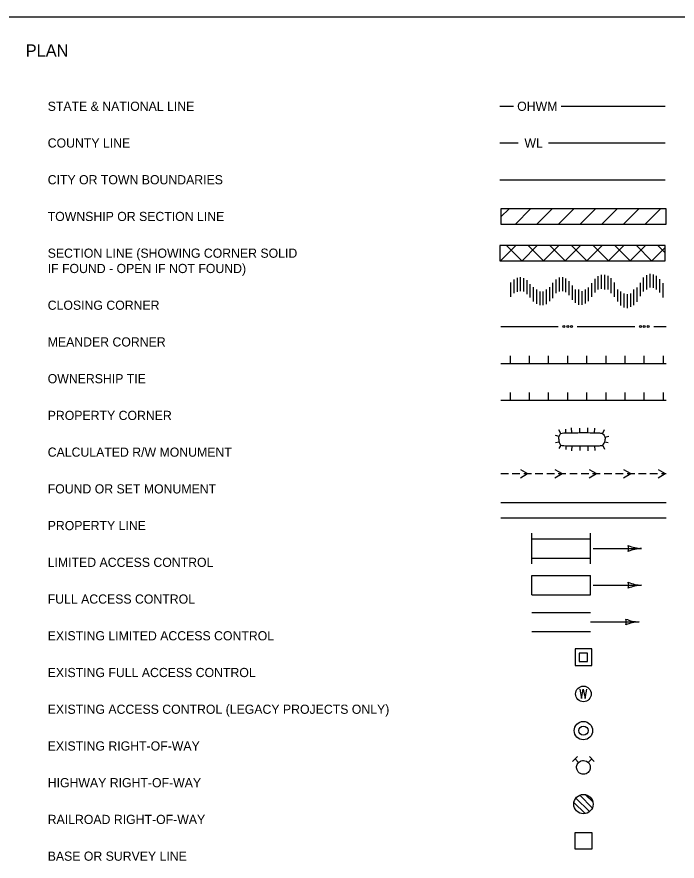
# Model space of a CAD drawing. Extents: x 49991.4 to 50021, y 49987.6 to 50011.4.
# Drawn here: x 50005.13 to 50009.45, y 49993.48 to 49999 of the extents above; entities that cross this region are included whole.
import ezdxf

# ---------------------------------------------------------------- set-up
doc = ezdxf.new("R2010")
doc.units = 0
doc.layers.add('Level 1', color=7, linetype='Continuous')
doc.layers.add('Level 2', color=7, linetype='Continuous')

msp = doc.modelspace()

# ---------------------------------------------------------------- linework, layer by layer
at = {"layer": 'Level 1'}
for p, q in [((50008.2879, 49998.4152), (50008.3758, 49998.4152)), ((50008.6879, 49998.4152), (50009.3679, 49998.4152)), ((50008.2879, 49998.1752), (50008.4057, 49998.1752)), ((50008.6047, 49998.1752), (50009.3679, 49998.1752)), ((50008.2879, 49997.9352), (50009.3679, 49997.9352)), ((50008.2935, 49997.6918), (50008.347, 49997.7452)), ((50009.3735, 49997.7452), (50008.2935, 49997.7452)), ((50008.2935, 49997.7452), (50008.2935, 49997.6452)), ((50008.3884, 49997.6452), (50008.4884, 49997.7452)), ((50008.5298, 49997.6452), (50008.6298, 49997.7452)), ((50008.6713, 49997.6452), (50008.7713, 49997.7452)), ((50008.8127, 49997.6452), (50008.9127, 49997.7452)), ((50008.9541, 49997.6452), (50009.0541, 49997.7452)), ((50009.0955, 49997.6452), (50009.1955, 49997.7452)), ((50009.2369, 49997.6452), (50009.3369, 49997.7452)), ((50009.3735, 49997.6452), (50009.3735, 49997.7452)), ((50008.2935, 49997.6452), (50009.3735, 49997.6452)), ((50009.3679, 49997.5052), (50008.2879, 49997.5052)), ((50008.2879, 49997.5052), (50008.2879, 49997.4052)), ((50008.2906, 49997.4052), (50008.3906, 49997.5052)), ((50008.3309, 49997.5052), (50008.4309, 49997.4052)), ((50008.432, 49997.4052), (50008.532, 49997.5052)), ((50008.4723, 49997.5052), (50008.5723, 49997.4052)), ((50008.5734, 49997.4052), (50008.6734, 49997.5052)), ((50008.6137, 49997.5052), (50008.7137, 49997.4052)), ((50008.7148, 49997.4052), (50008.8148, 49997.5052)), ((50008.7551, 49997.5052), (50008.8551, 49997.4052)), ((50008.8562, 49997.4052), (50008.9562, 49997.5052)), ((50008.8966, 49997.5052), (50008.9966, 49997.4052)), ((50008.9977, 49997.4052), (50009.0977, 49997.5052)), ((50009.038, 49997.5052), (50009.138, 49997.4052)), ((50009.1391, 49997.4052), (50009.2391, 49997.5052)), ((50009.1794, 49997.5052), (50009.2794, 49997.4052)), ((50009.2805, 49997.4052), (50009.3679, 49997.4926)), ((50009.3208, 49997.5052), (50009.3679, 49997.4582)), ((50009.3679, 49997.4052), (50009.3679, 49997.5052)), ((50008.2879, 49997.4068), (50008.2894, 49997.4052)), ((50008.2879, 49997.4052), (50009.3679, 49997.4052)), ((50008.3779, 49997.2838), (50008.3779, 49997.1935)), ((50008.3991, 49997.2932), (50008.3991, 49997.2034)), ((50008.4203, 49997.298), (50008.4203, 49997.208)), ((50008.4415, 49997.2924), (50008.4415, 49997.204)), ((50008.4626, 49997.2792), (50008.4626, 49997.188)), ((50008.6532, 49997.2835), (50008.6532, 49997.1945)), ((50008.6744, 49997.2959), (50008.6744, 49997.2058)), ((50008.6744, 49997.2956), (50008.6744, 49997.2061)), ((50008.6956, 49997.298), (50008.6956, 49997.208)), ((50008.7168, 49997.2908), (50008.7168, 49997.201)), ((50008.7379, 49997.2733), (50008.7379, 49997.1804)), ((50008.9073, 49997.2879), (50008.9073, 49997.1973)), ((50008.9285, 49997.3058), (50008.9285, 49997.2173)), ((50008.9497, 49997.3134), (50008.9497, 49997.2224)), ((50008.9709, 49997.3143), (50008.9709, 49997.2173)), ((50008.992, 49997.3064), (50008.992, 49997.2173)), ((50009.0132, 49997.2928), (50009.0132, 49997.1946)), ((50009.225, 49997.2953), (50009.225, 49997.2046)), ((50009.2462, 49997.3106), (50009.2462, 49997.2173)), ((50009.2673, 49997.3203), (50009.2673, 49997.2299)), ((50009.2885, 49997.3166), (50009.2885, 49997.2277)), ((50009.3097, 49997.3063), (50009.3097, 49997.2173)), ((50009.3309, 49997.285), (50009.3309, 49997.1974)), ((50008.3568, 49997.2631), (50008.3568, 49997.1702)), ((50008.4838, 49997.2528), (50008.4838, 49997.1656)), ((50008.505, 49997.2336), (50008.505, 49997.1395)), ((50008.5262, 49997.2173), (50008.5262, 49997.1245)), ((50008.5897, 49997.2173), (50008.5897, 49997.1231)), ((50008.6109, 49997.2322), (50008.6109, 49997.141)), ((50008.632, 49997.2615), (50008.632, 49997.161)), ((50008.7591, 49997.2441), (50008.7591, 49997.1507)), ((50008.7803, 49997.2173), (50008.7803, 49997.1313)), ((50008.8015, 49997.2173), (50008.8015, 49997.1169)), ((50008.8438, 49997.2173), (50008.8438, 49997.1266)), ((50008.865, 49997.2314), (50008.865, 49997.1417)), ((50008.8862, 49997.2593), (50008.8862, 49997.1693)), ((50009.0344, 49997.264), (50009.0344, 49997.1737)), ((50009.0344, 49997.2622), (50009.0344, 49997.1709)), ((50009.0556, 49997.2173), (50009.0556, 49997.1388)), ((50009.1615, 49997.2173), (50009.1615, 49997.1159)), ((50009.1826, 49997.2318), (50009.1826, 49997.1362)), ((50009.2038, 49997.2615), (50009.2038, 49997.1741)), ((50009.352, 49997.2601), (50009.352, 49997.1665)), ((50008.5473, 49997.205), (50008.5473, 49997.1157)), ((50008.5685, 49997.2047), (50008.5685, 49997.1146)), ((50008.8226, 49997.207), (50008.8226, 49997.1182)), ((50009.0768, 49997.2039), (50009.0768, 49997.1136)), ((50009.0979, 49997.1913), (50009.0979, 49997.1004)), ((50009.1191, 49997.1868), (50009.1191, 49997.0969)), ((50009.1403, 49997.1918), (50009.1403, 49997.1042)), ((50008.2935, 49996.9752), (50008.6685, 49996.9752)), ((50008.7935, 49996.9752), (50009.1685, 49996.9752)), ((50009.2935, 49996.9752), (50009.3735, 49996.9752)), ((50008.356, 49996.7352), (50008.356, 49996.7852)), ((50008.481, 49996.7352), (50008.481, 49996.7852)), ((50008.606, 49996.7352), (50008.606, 49996.7852)), ((50008.731, 49996.7352), (50008.731, 49996.7852)), ((50008.856, 49996.7352), (50008.856, 49996.7852)), ((50008.981, 49996.7352), (50008.981, 49996.7852)), ((50009.106, 49996.7352), (50009.106, 49996.7852)), ((50009.231, 49996.7352), (50009.231, 49996.7852)), ((50009.356, 49996.7352), (50009.356, 49996.7852)), ((50008.2935, 49996.7352), (50009.3735, 49996.7352)), ((50008.356, 49996.4952), (50008.356, 49996.5452)), ((50008.481, 49996.4952), (50008.481, 49996.5452)), ((50008.606, 49996.4952), (50008.606, 49996.5452)), ((50008.731, 49996.4952), (50008.731, 49996.5452)), ((50008.856, 49996.4952), (50008.856, 49996.5452)), ((50008.981, 49996.4952), (50008.981, 49996.5452)), ((50009.106, 49996.4952), (50009.106, 49996.5452)), ((50009.231, 49996.4952), (50009.231, 49996.5452)), ((50009.356, 49996.4952), (50009.356, 49996.5452)), ((50008.2935, 49996.4952), (50009.3735, 49996.4952)), ((50008.6851, 49996.276), (50008.6735, 49996.2999)), ((50008.7193, 49996.2809), (50008.7184, 49996.306)), ((50008.7567, 49996.2819), (50008.7565, 49996.3134)), ((50008.8107, 49996.2822), (50008.8106, 49996.3124)), ((50008.8615, 49996.2824), (50008.8617, 49996.3134)), ((50008.9068, 49996.2819), (50008.9075, 49996.3123)), ((50008.9575, 49996.2758), (50008.971, 49996.3027)), ((50008.6749, 49996.2583), (50008.6502, 49996.2629)), ((50008.9732, 49996.2229), (50008.9962, 49996.218)), ((50008.9735, 49996.2537), (50008.9989, 49996.2591)), ((50008.6749, 49996.2195), (50008.6502, 49996.2149)), ((50008.6851, 49996.2017), (50008.6735, 49996.1779)), ((50008.7193, 49996.1969), (50008.7184, 49996.1717)), ((50008.7567, 49996.1959), (50008.7565, 49996.1643)), ((50008.8107, 49996.1955), (50008.8106, 49996.1654)), ((50008.8615, 49996.1953), (50008.8617, 49996.1643)), ((50008.9068, 49996.1959), (50008.9075, 49996.1654)), ((50008.9575, 49996.202), (50008.971, 49996.1751)), ((50008.2935, 49996.0152), (50008.3435, 49996.0152)), ((50008.3685, 49996.0152), (50008.4185, 49996.0152)), ((50008.4211, 49996.0426), (50008.4685, 49996.0152)), ((50008.4211, 49995.9879), (50008.4685, 49996.0152)), ((50008.4435, 49996.0152), (50008.4935, 49996.0152)), ((50008.5185, 49996.0152), (50008.5685, 49996.0152)), ((50008.5935, 49996.0152), (50008.6435, 49996.0152)), ((50008.6461, 49996.0426), (50008.6935, 49996.0152)), ((50008.6461, 49995.9879), (50008.6935, 49996.0152)), ((50008.6685, 49996.0152), (50008.7185, 49996.0152)), ((50008.7435, 49996.0152), (50008.7935, 49996.0152)), ((50008.8185, 49996.0152), (50008.8685, 49996.0152)), ((50008.8711, 49996.0426), (50008.9185, 49996.0152)), ((50008.8711, 49995.9879), (50008.9185, 49996.0152)), ((50008.8935, 49996.0152), (50008.9435, 49996.0152)), ((50008.9685, 49996.0152), (50009.0185, 49996.0152)), ((50009.0435, 49996.0152), (50009.0935, 49996.0152)), ((50009.0961, 49996.0426), (50009.1435, 49996.0152)), ((50009.0961, 49995.9879), (50009.1435, 49996.0152)), ((50009.1185, 49996.0152), (50009.1685, 49996.0152)), ((50009.1935, 49996.0152), (50009.2435, 49996.0152)), ((50009.2685, 49996.0152), (50009.3185, 49996.0152)), ((50009.3211, 49996.0426), (50009.3685, 49996.0152)), ((50009.3211, 49995.9879), (50009.3685, 49996.0152)), ((50009.3435, 49996.0152), (50009.3735, 49996.0152)), ((50008.2935, 49995.8252), (50009.3735, 49995.8252)), ((50008.2935, 49995.7252), (50009.3735, 49995.7252)), ((50008.4956, 49995.588), (50008.4956, 49995.626)), ((50008.8798, 49995.588), (50008.8798, 49995.626)), ((50008.4956, 49995.588), (50008.8798, 49995.588)), ((50008.4956, 49995.463), (50008.4956, 49995.588)), ((50008.8798, 49995.463), (50008.8798, 49995.588)), ((50008.8965, 49995.5255), (50009.2137, 49995.5255)), ((50008.4956, 49995.425), (50008.4956, 49995.463)), ((50008.4956, 49995.463), (50008.8798, 49995.463)), ((50008.8798, 49995.425), (50008.8798, 49995.463)), ((50008.4956, 49995.348), (50008.8798, 49995.348)), ((50008.4956, 49995.223), (50008.4956, 49995.348)), ((50008.8798, 49995.223), (50008.8798, 49995.348)), ((50008.8965, 49995.2855), (50009.2137, 49995.2855)), ((50008.4956, 49995.223), (50008.8798, 49995.223)), ((50008.4956, 49995.108), (50008.8798, 49995.108)), ((50008.8798, 49995.0455), (50009.197, 49995.0455)), ((50008.4956, 49994.983), (50008.8798, 49994.983)), ((50008.888, 49994.8697), (50008.779, 49994.8697)), ((50008.779, 49994.8697), (50008.779, 49994.7607)), ((50008.888, 49994.7607), (50008.888, 49994.8697)), ((50008.8607, 49994.8424), (50008.8063, 49994.8424)), ((50008.8063, 49994.8424), (50008.8063, 49994.788)), ((50008.8607, 49994.788), (50008.8607, 49994.8424)), ((50008.779, 49994.7607), (50008.888, 49994.7607)), ((50008.8063, 49994.788), (50008.8607, 49994.788)), ((50008.8104, 49994.6062), (50008.8198, 49994.5462)), ((50008.8198, 49994.5462), (50008.8321, 49994.6062)), ((50008.8321, 49994.6062), (50008.8444, 49994.5462)), ((50008.8444, 49994.5462), (50008.8548, 49994.6062)), ((50008.7947, 49994.1662), (50008.7628, 49994.1343)), ((50008.8016, 49994.1273), (50008.7787, 49994.1502)), ((50008.7964, 49994.1206), (50008.8013, 49994.1267)), ((50008.8013, 49994.1267), (50008.8071, 49994.1317)), ((50008.8071, 49994.1317), (50008.8134, 49994.1355)), ((50008.8134, 49994.1355), (50008.8194, 49994.138)), ((50008.8194, 49994.138), (50008.8266, 49994.1397)), ((50008.8266, 49994.1397), (50008.834, 49994.1403)), ((50008.834, 49994.1403), (50008.8436, 49994.1391)), ((50008.8436, 49994.1391), (50008.8532, 49994.1357)), ((50008.8532, 49994.1357), (50008.8616, 49994.1303)), ((50008.8616, 49994.1303), (50008.8678, 49994.1244)), ((50008.8653, 49994.1273), (50008.8882, 49994.1502)), ((50008.8723, 49994.1662), (50008.9042, 49994.1343)), ((50008.7886, 49994.0919), (50008.7888, 49994.1001)), ((50008.7896, 49994.0852), (50008.7886, 49994.0919)), ((50008.7888, 49994.1001), (50008.7903, 49994.1079)), ((50008.7917, 49994.0789), (50008.7896, 49994.0852)), ((50008.7903, 49994.1079), (50008.7931, 49994.115)), ((50008.7964, 49994.0698), (50008.7917, 49994.0789)), ((50008.7931, 49994.115), (50008.7964, 49994.1206)), ((50008.8678, 49994.1244), (50008.873, 49994.1168)), ((50008.8728, 49994.0733), (50008.8697, 49994.0685)), ((50008.8753, 49994.0786), (50008.8728, 49994.0733)), ((50008.873, 49994.1168), (50008.8767, 49994.1078)), ((50008.8774, 49994.0853), (50008.8753, 49994.0786)), ((50008.8767, 49994.1078), (50008.8781, 49994.1011)), ((50008.8784, 49994.0919), (50008.8774, 49994.0853)), ((50008.8781, 49994.1011), (50008.8785, 49994.0955)), ((50008.8785, 49994.0955), (50008.8784, 49994.0919)), ((50008.799, 49994.0664), (50008.7964, 49994.0698)), ((50008.8028, 49994.0623), (50008.799, 49994.0664)), ((50008.8077, 49994.0583), (50008.8028, 49994.0623)), ((50008.8137, 49994.0545), (50008.8077, 49994.0583)), ((50008.8194, 49994.0525), (50008.8137, 49994.0545)), ((50008.8253, 49994.051), (50008.8194, 49994.0525)), ((50008.8313, 49994.0503), (50008.8253, 49994.051)), ((50008.8373, 49994.0504), (50008.8313, 49994.0503)), ((50008.8433, 49994.0513), (50008.8373, 49994.0504)), ((50008.8514, 49994.054), (50008.8433, 49994.0513)), ((50008.8584, 49994.0577), (50008.8514, 49994.054)), ((50008.8646, 49994.0627), (50008.8584, 49994.0577)), ((50008.8697, 49994.0685), (50008.8646, 49994.0627)), ((50008.8089, 49993.9131), (50008.8914, 49993.8306)), ((50008.848, 49993.9164), (50008.8947, 49993.8697)), ((50008.7716, 49993.8656), (50008.8441, 49993.7931)), ((50008.7848, 49993.8948), (50008.8731, 49993.8065)), ((50008.7785, 49993.6702), (50008.8885, 49993.6702)), ((50008.7785, 49993.5602), (50008.7785, 49993.6702)), ((50008.8885, 49993.6702), (50008.8885, 49993.5602)), ((50008.8885, 49993.5602), (50008.7785, 49993.5602))]:
    msp.add_line(p, q, dxfattribs=at)
msp.add_lwpolyline([(49999.3835, 49998.9992), (50016.7501, 49998.9992), (50016.7501, 49987.7988), (49999.3835, 49987.7988)], close=True, dxfattribs=at)
for centre, radius in [((50008.706, 49996.9752), 0.00635), ((50008.706, 49996.9752), 0.00635), ((50008.731, 49996.9752), 0.00635), ((50008.731, 49996.9752), 0.00635), ((50008.756, 49996.9752), 0.00635), ((50008.756, 49996.9752), 0.00635), ((50009.206, 49996.9752), 0.00635), ((50009.206, 49996.9752), 0.00635), ((50009.231, 49996.9752), 0.00635), ((50009.231, 49996.9752), 0.00635), ((50009.256, 49996.9752), 0.00635), ((50009.256, 49996.9752), 0.00635), ((50008.8335, 49994.5752), 0.0511), ((50008.8335, 49994.3352), 0.06), ((50008.8335, 49994.3352), 0.03), ((50008.8335, 49993.8553), 0.0631)]:
    msp.add_circle(centre, radius, dxfattribs=at)
for centre, radius, start, end in [((50009.0671, 49995.5255), 0.0626, 342.1388, 17.8612), ((50009.2242, 49995.7794), 0.2541, 247.456, 267.6395), ((50009.2268, 49995.2596), 0.2663, 92.8273, 112.0772), ((50009.0671, 49995.2855), 0.0626, 342.1388, 17.8612), ((50009.2242, 49995.5394), 0.2541, 247.456, 267.6395), ((50009.2268, 49995.0196), 0.2663, 92.8273, 112.0772), ((50009.0504, 49995.0455), 0.0626, 342.1388, 17.8612), ((50009.2075, 49995.2994), 0.2541, 247.456, 267.6395), ((50009.2101, 49994.7796), 0.2663, 92.8273, 112.0772)]:
    msp.add_arc(centre, radius, start, end, dxfattribs=at)
for points in [[(50008.6718, 49996.2389), (50008.675, 49996.2589), (50008.6851, 49996.276), (50008.7043, 49996.2803), (50008.7567, 49996.2819), (50008.8615, 49996.2824), (50008.9304, 49996.2813), (50008.9593, 49996.2749), (50008.9747, 49996.2477), (50008.9755, 49996.2389)], [(50008.6718, 49996.2389), (50008.675, 49996.2189), (50008.6851, 49996.2017), (50008.7043, 49996.1975), (50008.7567, 49996.1959), (50008.8615, 49996.1953), (50008.9304, 49996.1964), (50008.9593, 49996.2028), (50008.9747, 49996.2301), (50008.9755, 49996.2389)]]:
    msp.add_spline(points, degree=3, dxfattribs=at)

# ---------------------------------------------------------------- texts
at = {"layer": 'Level 2'}
for s, height, p in [('PLAN', 0.08, (50005.187, 49998.7392)), ('STATE & NATIONAL LINE    ', 0.059999, (50005.3308, 49998.3852)), ('OHWM', 0.06, (50008.4003, 49998.3852)), ('COUNTY LINE         ', 0.059999, (50005.3308, 49998.1452)), ('WL', 0.06, (50008.4478, 49998.1452)), ('CITY OR TOWN BOUNDARIES  ', 0.059999, (50005.3308, 49997.9052)), ('TOWNSHIP OR SECTION LINE       ', 0.059999, (50005.3308, 49997.6652)), ('SECTION LINE (SHOWING CORNER SOLID      ', 0.059999, (50005.3308, 49997.4252)), ('IF FOUND - OPEN IF NOT FOUND)           ', 0.059999, (50005.3308, 49997.3252)), ('CLOSING CORNER           ', 0.059999, (50005.3308, 49997.0852)), ('MEANDER CORNER           ', 0.059999, (50005.3308, 49996.8452)), ('OWNERSHIP TIE            ', 0.059999, (50005.3308, 49996.6052)), ('PROPERTY CORNER                         ', 0.059999, (50005.3308, 49996.3652)), ('CALCULATED R/W MONUMENT                   ', 0.059999, (50005.3308, 49996.1252)), ('FOUND OR SET MONUMENT                        ', 0.059999, (50005.3308, 49995.8852)), ('PROPERTY LINE                           ', 0.059999, (50005.3308, 49995.6453)), ('LIMITED ACCESS CONTROL          ', 0.059999, (50005.3308, 49995.4052)), ('FULL ACCESS CONTROL          ', 0.059999, (50005.3308, 49995.1652)), ('EXISTING LIMITED ACCESS CONTROL          ', 0.059999, (50005.3308, 49994.9252)), ('EXISTING FULL ACCESS CONTROL         ', 0.059999, (50005.3308, 49994.6852)), ('EXISTING ACCESS CONTROL (LEGACY PROJECTS ONLY)          ', 0.059999, (50005.3308, 49994.4452)), ('EXISTING RIGHT-OF-WAY    ', 0.059999, (50005.3308, 49994.2052)), ('HIGHWAY RIGHT-OF-WAY', 0.059999, (50005.3308, 49993.9652)), ('RAILROAD RIGHT-OF-WAY    ', 0.059999, (50005.3308, 49993.7252)), ('BASE OR SURVEY LINE ', 0.059999, (50005.3308, 49993.4852))]:
    msp.add_text(s, height=height, dxfattribs=at).set_placement(p)

doc.saveas('drawing.dxf')
